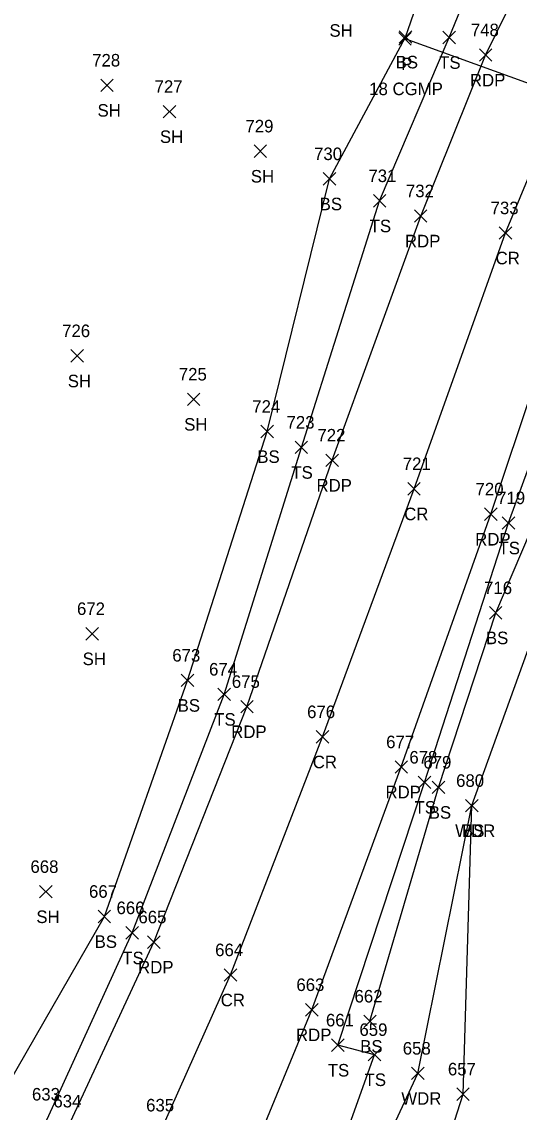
# Model space of a CAD drawing. Extents: x 1586965 to 1590952, y 716317 to 720029.
# Drawn here: x 1587122.8 to 1587202.1, y 719388.4 to 719562.4 of the extents above; entities that cross this region are included whole.
import ezdxf

# ---------------------------------------------------------------- set-up
doc = ezdxf.new("R2010")
doc.units = 0
for name, color, linetype in [('D_A', 7, 'Continuous'), ('D_C', 7, 'Continuous'), ('D_TIC', 7, 'Continuous'), ('DCP', 7, 'Continuous'), ('L_A', 7, 'Continuous'), ('L_I', 7, 'Continuous'), ('L_TIC', 7, 'Continuous'), ('LAWA', 7, 'Continuous'), ('LELB', 7, 'Continuous'), ('P_A', 7, 'Continuous'), ('P_I', 7, 'Continuous'), ('P_TIC', 7, 'Continuous'), ('PET', 7, 'Continuous'), ('PRC', 7, 'Continuous')]:
    doc.layers.add(name, color=color, linetype=linetype)

msp = doc.modelspace()

# ---------------------------------------------------------------- linework, layer by layer
at = {"layer": 'D_TIC'}
for points in [[(1587182.87, 719558.68), (1587184.87, 719560.68)], [(1587184.87, 719558.68), (1587182.87, 719560.68)]]:
    msp.add_lwpolyline(points, dxfattribs=at)
at = {"layer": 'DCP'}
msp.add_lwpolyline([(1587223.53, 719545.3), (1587183.87, 719559.68)], dxfattribs=at)
at = {"layer": 'L_TIC'}
for points in [[(1587182.93, 719558.95), (1587184.93, 719560.95)], [(1587184.93, 719558.95), (1587182.93, 719560.95)], [(1587189.9, 719558.88), (1587191.9, 719560.88)], [(1587191.9, 719558.88), (1587189.9, 719560.88)], [(1587135.36, 719551.25), (1587137.36, 719553.25)], [(1587137.36, 719551.25), (1587135.36, 719553.25)], [(1587145.31, 719547.05), (1587147.31, 719549.05)], [(1587147.31, 719547.05), (1587145.31, 719549.05)], [(1587159.8, 719540.74), (1587161.8, 719542.74)], [(1587161.8, 719540.74), (1587159.8, 719542.74)], [(1587170.82, 719536.32), (1587172.82, 719538.32)], [(1587172.82, 719536.32), (1587170.82, 719538.32)], [(1587178.82, 719532.81), (1587180.82, 719534.81)], [(1587180.82, 719532.81), (1587178.82, 719534.81)], [(1587130.62, 719508.08), (1587132.62, 719510.08)], [(1587132.62, 719508.08), (1587130.62, 719510.08)], [(1587149.17, 719501.16), (1587151.17, 719503.16)], [(1587151.17, 719501.16), (1587149.17, 719503.16)], [(1587160.88, 719496.01), (1587162.88, 719498.01)], [(1587162.88, 719496.01), (1587160.88, 719498.01)], [(1587166.34, 719493.49), (1587168.34, 719495.49)], [(1587168.34, 719493.49), (1587166.34, 719495.49)], [(1587199.36, 719481.43), (1587201.36, 719483.43)], [(1587201.36, 719481.43), (1587199.36, 719483.43)], [(1587197.32, 719467.09), (1587199.32, 719469.09)], [(1587199.32, 719467.09), (1587197.32, 719469.09)], [(1587132.99, 719463.75), (1587134.99, 719465.75)], [(1587134.99, 719463.75), (1587132.99, 719465.75)], [(1587148.18, 719456.32), (1587150.18, 719458.32)], [(1587150.18, 719456.32), (1587148.18, 719458.32)], [(1587154.04, 719454.09), (1587156.04, 719456.09)], [(1587156.04, 719454.09), (1587154.04, 719456.09)], [(1587185.97, 719440.05), (1587187.97, 719442.05)], [(1587187.97, 719440.05), (1587185.97, 719442.05)], [(1587188.21, 719439.25), (1587190.21, 719441.25)], [(1587190.21, 719439.25), (1587188.21, 719441.25)], [(1587193.51, 719436.33), (1587195.51, 719438.33)], [(1587195.51, 719436.33), (1587193.51, 719438.33)], [(1587193.51, 719436.33), (1587195.51, 719438.33)], [(1587195.51, 719436.33), (1587193.51, 719438.33)], [(1587125.62, 719422.6), (1587127.62, 719424.6)], [(1587127.62, 719422.6), (1587125.62, 719424.6)], [(1587134.94, 719418.64), (1587136.94, 719420.64)], [(1587136.94, 719418.64), (1587134.94, 719420.64)], [(1587139.39, 719416.03), (1587141.39, 719418.03)], [(1587141.39, 719416.03), (1587139.39, 719418.03)], [(1587177.28, 719401.93), (1587179.28, 719403.93)], [(1587179.28, 719401.93), (1587177.28, 719403.93)], [(1587172.15, 719398.12), (1587174.15, 719400.12)], [(1587174.15, 719398.12), (1587172.15, 719400.12)], [(1587178.01, 719396.6), (1587180.01, 719398.6)], [(1587180.01, 719396.6), (1587178.01, 719398.6)], [(1587184.92, 719393.62), (1587186.92, 719395.62)], [(1587186.92, 719393.62), (1587184.92, 719395.62)], [(1587192.11, 719390.3), (1587194.11, 719392.3)], [(1587194.11, 719390.3), (1587192.11, 719392.3)]]:
    msp.add_lwpolyline(points, dxfattribs=at)
at = {"layer": 'LAWA'}
msp.add_lwpolyline([(1587171.91, 719364.5), (1587185.92, 719394.62), (1587194.51, 719437.33), (1587204.69, 719465.5), (1587209.04, 719470.1), (1587216.07, 719486.45), (1587218.68, 719500.05), (1587226.66, 719522.84), (1587234.63, 719543.06), (1587243.18, 719549.48), (1587251, 719567.85), (1587260.43, 719579.32), (1587269.2, 719595.73), (1587274.23, 719603.67), (1587301.03, 719598.43), (1587318.82, 719602.47), (1587334.94, 719606.57), (1587351.65, 719607.7), (1587367.28, 719615.21), (1587401.27, 719626.51), (1587435.01, 719634.6)], dxfattribs=at)
at = {"layer": 'LELB'}
for points in [[(1586974.22, 719201.38), (1587004.64, 719224.97), (1587038.23, 719264.63), (1587070.35, 719308.83), (1587101.6, 719349.88), (1587119.36, 719390.75), (1587135.94, 719419.64), (1587149.18, 719457.32), (1587161.88, 719497.01), (1587171.82, 719537.32), (1587183.93, 719559.95), (1587196.31, 719595.67), (1587210.79, 719616.33), (1587226.54, 719644.19), (1587252.78, 719668.03), (1587275.41, 719699.75), (1587291.25, 719715.32), (1587307.92, 719729.13), (1587319.25, 719735.05), (1587320, 719753.34), (1587323.07, 719768.88), (1587320.57, 719781.92), (1587330.74, 719804.48), (1587340.87, 719823.38)], [(1586974.22, 719201.38), (1587004.64, 719224.97), (1587038.23, 719264.63), (1587070.35, 719308.83), (1587101.6, 719349.88), (1587119.36, 719390.75), (1587135.94, 719419.64), (1587149.18, 719457.32), (1587161.88, 719497.01), (1587171.82, 719537.32), (1587183.93, 719559.95), (1587196.31, 719595.67), (1587210.79, 719616.33), (1587226.54, 719644.19), (1587252.78, 719668.03), (1587275.41, 719699.75), (1587291.25, 719715.32), (1587307.92, 719729.13), (1587319.25, 719735.05), (1587320, 719753.34), (1587323.07, 719768.88), (1587320.57, 719781.92), (1587330.74, 719804.48), (1587340.87, 719823.38)], [(1586978.66, 719194.77), (1587009.14, 719220.21), (1587042.41, 719260.62), (1587074.55, 719306.69), (1587105.59, 719347.25), (1587126.81, 719387.29), (1587140.39, 719417.03), (1587155.04, 719455.09), (1587167.34, 719494.49), (1587179.82, 719533.81), (1587190.9, 719559.88), (1587204.29, 719592.61), (1587216.76, 719611.7), (1587236.63, 719636.62), (1587258.85, 719661.96), (1587283.81, 719691.81), (1587311.82, 719715.76), (1587323.53, 719725.34), (1587349.89, 719742.95), (1587377.37, 719757.84), (1587414.05, 719779.22)], [(1586978.66, 719194.77), (1587009.14, 719220.21), (1587042.41, 719260.62), (1587074.55, 719306.69), (1587105.59, 719347.25), (1587126.81, 719387.29), (1587140.39, 719417.03), (1587155.04, 719455.09), (1587167.34, 719494.49), (1587179.82, 719533.81), (1587190.9, 719559.88), (1587204.29, 719592.61), (1587216.76, 719611.7), (1587236.63, 719636.62), (1587258.85, 719661.96), (1587283.81, 719691.81), (1587311.82, 719715.76), (1587323.53, 719725.34), (1587349.89, 719742.95), (1587377.37, 719757.84), (1587414.05, 719779.22)], [(1587111.95, 719287.48), (1587133.61, 719303.61), (1587148.92, 719323.42), (1587167.88, 719366.46), (1587179.01, 719397.6), (1587173.15, 719399.12), (1587186.97, 719441.05), (1587200.36, 719482.43), (1587215.71, 719524.53), (1587222.82, 719545.46), (1587239.38, 719574.3), (1587247.92, 719589.42), (1587267.49, 719614.08), (1587286.95, 719636.16), (1587313.61, 719660.46), (1587335.34, 719679.69), (1587361.68, 719697.91), (1587398.24, 719722.21), (1587438.94, 719742.74)], [(1587111.95, 719287.48), (1587133.61, 719303.61), (1587148.92, 719323.42), (1587167.88, 719366.46), (1587179.01, 719397.6), (1587173.15, 719399.12), (1587186.97, 719441.05), (1587200.36, 719482.43), (1587215.71, 719524.53), (1587222.82, 719545.46), (1587239.38, 719574.3), (1587247.92, 719589.42), (1587267.49, 719614.08), (1587286.95, 719636.16), (1587313.61, 719660.46), (1587335.34, 719679.69), (1587361.68, 719697.91), (1587398.24, 719722.21), (1587438.94, 719742.74)], [(1587178.28, 719402.93), (1587189.21, 719440.25), (1587198.32, 719468.09), (1587203.86, 719481.06), (1587218.12, 719523.56), (1587224.35, 719543.95), (1587223.87, 719544.83), (1587224.18, 719545.53), (1587225.1, 719545.69), (1587240.99, 719573.37), (1587249.54, 719588.04), (1587270.51, 719611.5), (1587289.99, 719633.55), (1587315.89, 719657.91), (1587337.85, 719676.76), (1587363.47, 719694.64), (1587400.93, 719718.94), (1587441.36, 719738.52)], [(1587178.28, 719402.93), (1587189.21, 719440.25), (1587198.32, 719468.09), (1587203.86, 719481.06), (1587218.12, 719523.56), (1587224.35, 719543.95), (1587223.87, 719544.83), (1587224.18, 719545.53), (1587225.1, 719545.69), (1587240.99, 719573.37), (1587249.54, 719588.04), (1587270.51, 719611.5), (1587289.99, 719633.55), (1587315.89, 719657.91), (1587337.85, 719676.76), (1587363.47, 719694.64), (1587400.93, 719718.94), (1587441.36, 719738.52)], [(1587162.35, 719315.42), (1587177.91, 719360.08), (1587187.65, 719374.23), (1587193.11, 719391.3), (1587194.51, 719437.33)], [(1587162.35, 719315.42), (1587177.91, 719360.08), (1587187.65, 719374.23), (1587193.11, 719391.3), (1587194.51, 719437.33)]]:
    msp.add_lwpolyline(points, dxfattribs=at)
at = {"layer": 'P_TIC'}
for points in [[(1587195.72, 719556.08), (1587197.72, 719558.08)], [(1587197.72, 719556.08), (1587195.72, 719558.08)], [(1587185.37, 719530.4), (1587187.37, 719532.4)], [(1587187.37, 719530.4), (1587185.37, 719532.4)], [(1587198.88, 719527.69), (1587200.88, 719529.69)], [(1587200.88, 719527.69), (1587198.88, 719529.69)], [(1587171.27, 719491.43), (1587173.27, 719493.43)], [(1587173.27, 719491.43), (1587171.27, 719493.43)], [(1587184.3, 719486.87), (1587186.3, 719488.87)], [(1587186.3, 719486.87), (1587184.3, 719488.87)], [(1587196.56, 719482.83), (1587198.56, 719484.83)], [(1587198.56, 719482.83), (1587196.56, 719484.83)], [(1587157.67, 719452.12), (1587159.67, 719454.12)], [(1587159.67, 719452.12), (1587157.67, 719454.12)], [(1587169.73, 719447.3), (1587171.73, 719449.3)], [(1587171.73, 719447.3), (1587169.73, 719449.3)], [(1587182.27, 719442.5), (1587184.27, 719444.5)], [(1587184.27, 719442.5), (1587182.27, 719444.5)], [(1587142.83, 719414.56), (1587144.83, 719416.56)], [(1587144.83, 719414.56), (1587142.83, 719416.56)], [(1587155.05, 719409.32), (1587157.05, 719411.32)], [(1587157.05, 719409.32), (1587155.05, 719411.32)], [(1587168, 719403.76), (1587170, 719405.76)], [(1587170, 719403.76), (1587168, 719405.76)]]:
    msp.add_lwpolyline(points, dxfattribs=at)
at = {"layer": 'PET'}
for points in [[(1586981.32, 719191.44), (1587010.72, 719218.17), (1587046.97, 719256.26), (1587081.9, 719302.22), (1587109.59, 719344.47), (1587130.23, 719386.19), (1587143.83, 719415.56), (1587158.67, 719453.12), (1587172.27, 719492.43), (1587186.37, 719531.4), (1587196.72, 719557.08), (1587212.09, 719588.4), (1587223.39, 719607.14), (1587242.2, 719632.56), (1587263.71, 719657.85), (1587289.89, 719684.48), (1587313.81, 719705.37), (1587345, 719730.07), (1587380.68, 719751.95), (1587418.28, 719771.56)], [(1586998.3, 719170.55), (1587031.46, 719201.5), (1587048.24, 719215.72), (1587069.37, 719240.81), (1587083.56, 719258.07), (1587104.56, 719290.21), (1587133.86, 719331.71), (1587155.62, 719372.22), (1587169, 719404.76), (1587183.27, 719443.5), (1587197.56, 719483.83), (1587211.74, 719526.3), (1587221.19, 719546.28), (1587236.84, 719576.04), (1587246.13, 719590.54), (1587264.51, 719616.23), (1587283.97, 719638.96), (1587310.1, 719664.5), (1587332.49, 719682.99), (1587358.98, 719703.31), (1587395.82, 719726.18), (1587435.88, 719747.89)]]:
    msp.add_lwpolyline(points, dxfattribs=at)
at = {"layer": 'PRC'}
msp.add_lwpolyline([(1586989.8, 719181.42), (1587021.35, 719209.83), (1587057.54, 719247.82), (1587093.64, 719295.06), (1587121.6, 719338.75), (1587145.01, 719385.55), (1587156.05, 719410.32), (1587170.73, 719448.3), (1587185.3, 719487.87), (1587199.88, 719528.69), (1587209.21, 719551.28), (1587224.26, 719582.11), (1587235.22, 719599.27), (1587253.6, 719624.57), (1587274.17, 719648.49), (1587299.95, 719674.27), (1587323.51, 719694.22), (1587352.02, 719715.49), (1587388.91, 719738.13), (1587428.57, 719759.37)], dxfattribs=at)
msp.add_lwpolyline([(1586989.8, 719181.42), (1587021.35, 719209.83), (1587057.54, 719247.82), (1587093.64, 719295.06), (1587121.6, 719338.75), (1587145.01, 719385.55), (1587156.05, 719410.32), (1587170.73, 719448.3), (1587185.3, 719487.87), (1587199.88, 719528.69), (1587209.21, 719551.28), (1587224.26, 719582.11), (1587235.22, 719599.27), (1587253.6, 719624.57), (1587274.17, 719648.49), (1587299.95, 719674.27), (1587323.51, 719694.22), (1587352.02, 719715.49), (1587388.91, 719738.13), (1587428.57, 719759.37)], dxfattribs=at)

# ---------------------------------------------------------------- texts
at = {"layer": 'D_A'}
msp.add_text('P', height=2, dxfattribs=at).set_placement((1587183.25, 719554.68))
at = {"layer": 'D_C'}
msp.add_text('18 CGMP', height=2, dxfattribs=at).set_placement((1587178.16, 719550.68))
at = {"layer": 'L_A'}
for s, p in [('SH', (1587171.82, 719560)), ('BS', (1587182.37, 719554.95)), ('TS', (1587189.31, 719554.88)), ('SH', (1587134.85, 719547.25)), ('SH', (1587144.8, 719543.05)), ('SH', (1587159.29, 719536.74)), ('BS', (1587170.26, 719532.32)), ('TS', (1587178.23, 719528.81)), ('SH', (1587130.11, 719504.08)), ('SH', (1587148.66, 719497.16)), ('BS', (1587160.32, 719492.01)), ('TS', (1587165.75, 719489.49)), ('TS', (1587198.77, 719477.43)), ('BS', (1587196.76, 719463.09)), ('SH', (1587132.48, 719459.75)), ('BS', (1587147.62, 719452.32)), ('TS', (1587153.45, 719450.09)), ('TS', (1587185.38, 719436.05)), ('BS', (1587187.65, 719435.25)), ('BS', (1587192.95, 719432.33)), ('WDR', (1587191.87, 719432.33)), ('SH', (1587125.1, 719418.6)), ('BS', (1587134.39, 719414.64)), ('TS', (1587138.8, 719412.03)), ('BS', (1587176.72, 719397.93)), ('TS', (1587171.56, 719394.12)), ('TS', (1587177.42, 719392.6)), ('WDR', (1587183.28, 719389.62))]:
    msp.add_text(s, height=2, dxfattribs=at).set_placement(p)
at = {"layer": 'L_I'}
for s, p in [('728', (1587134, 719555.25)), ('727', (1587143.95, 719551.05)), ('729', (1587158.43, 719544.74)), ('730', (1587169.37, 719540.32)), ('731', (1587178.03, 719536.81)), ('726', (1587129.21, 719512.08)), ('725', (1587147.81, 719505.16)), ('724', (1587159.52, 719500.01)), ('723', (1587164.98, 719497.49)), ('719', (1587198.55, 719485.43)), ('716', (1587196.47, 719471.09)), ('672', (1587131.58, 719467.75)), ('673', (1587146.77, 719460.32)), ('674', (1587152.63, 719458.09)), ('678', (1587184.56, 719444.05)), ('679', (1587186.79, 719443.25)), ('680', (1587192.01, 719440.33)), ('680', (1587192.01, 719440.33)), ('668', (1587124.16, 719426.6)), ('667', (1587133.49, 719422.64)), ('666', (1587137.88, 719420.03)), ('662', (1587175.82, 719405.93)), ('661', (1587171.26, 719402.12)), ('659', (1587176.6, 719400.6)), ('658', (1587183.51, 719397.62)), ('657', (1587190.7, 719394.3)), ('633', (1587124.4, 719390.29))]:
    msp.add_text(s, height=2, dxfattribs=at).set_placement(p)
at = {"layer": 'P_A'}
for s, p in [('RDP', (1587194.21, 719552.08)), ('RDP', (1587183.86, 719526.4)), ('CR', (1587198.31, 719523.69)), ('RDP', (1587169.75, 719487.43)), ('CR', (1587183.73, 719482.87)), ('RDP', (1587195.05, 719478.83)), ('RDP', (1587156.16, 719448.12)), ('CR', (1587169.16, 719443.3)), ('RDP', (1587180.75, 719438.5)), ('RDP', (1587141.32, 719410.56)), ('CR', (1587154.49, 719405.32)), ('RDP', (1587166.49, 719399.76))]:
    msp.add_text(s, height=2, dxfattribs=at).set_placement(p)
at = {"layer": 'P_I'}
for s, p in [('748', (1587194.36, 719560.08)), ('732', (1587184.01, 719534.4)), ('733', (1587197.51, 719531.69)), ('722', (1587169.9, 719495.43)), ('721', (1587183.5, 719490.87)), ('720', (1587195.11, 719486.83)), ('675', (1587156.26, 719456.12)), ('676', (1587168.26, 719451.3)), ('677', (1587180.86, 719446.5)), ('665', (1587141.37, 719418.56)), ('664', (1587153.6, 719413.32)), ('663', (1587166.55, 719407.76)), ('634', (1587127.82, 719389.19)), ('635', (1587142.6, 719388.55))]:
    msp.add_text(s, height=2, dxfattribs=at).set_placement(p)

doc.saveas('drawing.dxf')
